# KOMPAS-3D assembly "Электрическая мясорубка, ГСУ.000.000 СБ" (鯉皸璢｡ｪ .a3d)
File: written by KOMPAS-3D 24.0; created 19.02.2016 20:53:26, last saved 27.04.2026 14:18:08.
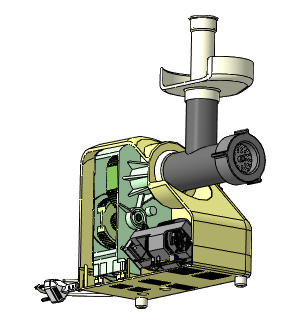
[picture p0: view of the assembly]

Document properties: Автор: Аня; Полное имя файла: C:\Users\USG_411.STUD\Desktop\ГМ2704_411-23\Мясорубка.a3d

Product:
- Component [detail]: Основание корпуса  | pos. 1  | Материал: Фторопласт-4  ГОСТ 10007-80 Е (density 2200 kg/m3); Масса: 0.272568; Автор: Аня; source file: Задание_ГМ-личная номинация\Задание_ВУЗ\Модели\Основание корпуса.m3d
- Component [detail]: Амортизатор  | pos. 10  | Масса: 0.016894; Автор: Аня; source file: Задание_ГМ-личная номинация\Задание_ВУЗ\Модели\Амортизатор (4 шт).m3d
- Component [detail]: Амортизатор  | pos. 11  | Масса: 0.016894; Автор: Аня; source file: Задание_ГМ-личная номинация\Задание_ВУЗ\Модели\Амортизатор (4 шт).m3d
- Component [detail]: Амортизатор  | pos. 12  | Масса: 0.016894; Автор: Аня; source file: Задание_ГМ-личная номинация\Задание_ВУЗ\Модели\Амортизатор (4 шт).m3d
- Component [detail]: Амортизатор  | pos. 13  | Масса: 0.016894; Автор: Аня; source file: Задание_ГМ-личная номинация\Задание_ВУЗ\Модели\Амортизатор (4 шт).m3d
- Component [detail]: Подушечка  | pos. 14  | Масса: 0.003215; Автор: Аня; source file: Задание_ГМ-личная номинация\Задание_ВУЗ\Модели\Подушечка .m3d
- Component [detail]: Подушечка  | pos. 15  | Масса: 0.003215; Автор: Аня; source file: Задание_ГМ-личная номинация\Задание_ВУЗ\Модели\Подушечка .m3d
- Component [detail]: Подушечка  | pos. 16  | Масса: 0.003215; Автор: Аня; source file: Задание_ГМ-личная номинация\Задание_ВУЗ\Модели\Подушечка .m3d
- Component [detail]: Подушечка  | pos. 17  | Масса: 0.003215; Автор: Аня; source file: Задание_ГМ-личная номинация\Задание_ВУЗ\Модели\Подушечка .m3d
- Component [detail]: Подушечка  | pos. 18  | Масса: 0.003215; Автор: Аня; source file: Задание_ГМ-личная номинация\Задание_ВУЗ\Модели\Подушечка .m3d
- Component [detail]: Подушечка  | pos. 19  | Масса: 0.003215; Автор: Аня; source file: Задание_ГМ-личная номинация\Задание_ВУЗ\Модели\Подушечка .m3d
- Component [detail]: Подушечка  | pos. 20  | Масса: 0.003215; Автор: Аня; source file: Задание_ГМ-личная номинация\Задание_ВУЗ\Модели\Подушечка .m3d
- Component [detail]: Подушечка  | pos. 21  | Масса: 0.003215; Автор: Аня; source file: Задание_ГМ-личная номинация\Задание_ВУЗ\Модели\Подушечка .m3d
- Component [assembly]: Редуктор  | pos. 2  | Масса: 2.986384; Автор: Аня; source file: Задание_ГМ-личная номинация\Задание_ВУЗ\Модели\Сборка редуктора.a3d
- Component [assembly]: Выключатель  | pos. 4  | Масса: 0.033755; Автор: Аня; source file: Задание_ГМ-личная номинация\Задание_ВУЗ\Модели\Выключатель.a3d
- Component [detail]: Плата  | pos. 5  | Масса: 0.019638; Автор: Аня; source file: Задание_ГМ-личная номинация\Задание_ВУЗ\Модели\Плата.m3d
- Component [assembly]: Сборка внешних деталей мясорубки  | pos. 6  | Масса: 5.888839; Автор: Аня; source file: Задание_ГМ-личная номинация\Задание_ВУЗ\Модели\Вторая сборка.a3d
- Component [detail]: Стопорный болт  | pos. 7  | Масса: 0.088582; Автор: Аня; source file: Задание_ГМ-личная номинация\Задание_ВУЗ\Модели\Стопорный болт.m3d
- Component [detail]: Вилка  | pos. 8  | Масса: 0.091381; Автор: Аня; source file: Задание_ГМ-личная номинация\Задание_ВУЗ\Модели\Вилка.m3d
- Component [detail]: Держатель провода  | pos. 9  | Масса: 0.003792; Автор: Аня; source file: Задание_ГМ-личная номинация\Задание_ВУЗ\Модели\Держатель провода.m3d
- Body: Тело 3  | qty 1
    Масса: 0.039235
- Component [standard]: Шайба A 4 ГОСТ 6958-78  | qty 4  | Масса: 0.000774; Раздел спецификации: Стандартные изделия; Рассекать на разрезах: no
- Component [standard]: Шуруп 1-4x20.019 ГОСТ 1144-80  | qty 4  | pos. 36  | Материал: Сталь 08кп ГОСТ 1050-2013 (density 7871 kg/m3); Масса: 0.00198; Раздел спецификации: Стандартные изделия; Рассекать на разрезах: no; additional columns: BOSimple***Material:aed9f2af-caf6-4059-826c-b94d4af93e47
- Component [assembly]: Двигатель  | designation ГСУ.001.000  | qty 1  | Масса: 0.738912; Автор: USG_411; source file: Двигатель мясорубки\ГСУ.001.000 ЭСБ - Двигатель.a3d
- Part/product: Электрическая мясорубка  | designation ГСУ.000.000 СБ
    Масса: 9.517468

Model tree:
1. Сечение поверхностью:1
2. Смещенная плоскость:1
     Расстояние = 15
3. Смещенная плоскость:2
     Расстояние = 63
4. Эскиз:1
5. Эскиз:3  (with: Грань.Операция выдавливания:2)
6. Эскиз:4  (with: Грань.Операция выдавливания:6, Ребро.Операция выдавливания:6)
7. Эскиз:6  (with: Грань.Операция выдавливания:2, Ребро.Вырезать элемент выдавливания:14)
8. Эскиз:7  (with: Грань.Вырезать элемент выдавливания:1, Ребро.Вырезать элемент выдавливания:2)
9. Смещенная плоскость:3  (with: Грань.Операция выдавливания:2)
     Расстояние = 12
10. Эскиз:8  (with: Ребро.Операция выдавливания:1)
11. Эскиз:9  (with: Грань.Операция выдавливания:6, Ребро.Вырезать элемент выдавливания:14)
12. Эскиз:10  (with: Грань.Операция выдавливания:2, Ребро.Вырезать элемент выдавливания:14)
13. Эскиз:11  (with: Грань.Операция выдавливания:2)
14. Эскиз:12  (with: Грань.Операция выдавливания:7)
15. Эскиз:13  (with: Грань.Операция выдавливания:1, Ребро.Вырезать элемент выдавливания:20)
16. Сплайн:4
     Координата X = 24.0569; Координата Y = 47.5876; Координата Z = 4.9171; Координата X = -2.76426; Координата Y = 55.0577; Координата Z = 3.36768; Координата X = -16.3145; Координата Y = 63.0116; Координата Z = 3; Координата X = -38.7823; Координата Y = 63; Координата Z = 2.99512; Координата X = -61.2823; Координата Y = 63; Координата Z = 2.99512; Координата X = -82; Координата Y = 30.4165; Координата Z = -3.17361; Координата X = -100; Координата Z = -10; Координата X = -102; Координата Z = -10; Координата X = -120.657; Координата Y = -31.7341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
17. Кинематическая операция:3
     Длина траектории = 519.475
18. Эскиз:14  (with: Грань.Кинематическая операция:3)
19. Эскиз:15  (with: Грань.Операция выдавливания:2)
20. Смещенная плоскость:5  (with: Грань.Вырезать элемент выдавливания:1)
     Расстояние = 3
21. Эскиз:16
22. Эскиз:17  (with: Грань.Кинематическая операция:3)
23. Смещенная плоскость:6  (with: Грань.Операция выдавливания:1)
     Расстояние = 2
24. Эскиз:20
25. Сплайн:7
     Координата X = 24.0569; Координата Y = 46.8619; Координата Z = 4.87679; Координата X = 24.0569; Координата Y = 38.923; Координата Z = -0.744157; Координата X = 9.1117; Координата Y = 32; Координата Z = -6.60744; Порядок = 4
26. Кинематическая операция:7
     Длина траектории = 28.248
27. Эскиз:21  (with: Грань.Операция выдавливания:1, Ребро.Операция выдавливания:1)
28. Эскиз:22  (with: Грань.Кинематическая операция:3)
29. Смещенная плоскость:7  (with: Грань.Операция выдавливания:2)
     Расстояние = 2
30. Смещенная плоскость:8  (with: Грань.Вырезать элемент выдавливания:1)
     Расстояние = 7
31. Эскиз:24
32. Эскиз:26
33. Сплайн:9
     Координата X = 24.0569; Координата Y = 48.3019; Координата Z = 4.84943; Координата X = 34.1389; Координата Y = 35.7895; Координата Z = 8; Координата X = 50.0249; Координата Y = 30.353; Координата Z = 8; Координата X = 53.724; Координата Y = 30.4898; Координата Z = 4; Координата X = 46.724; Координата Y = 30.4898; Координата Z = 4; Порядок = 4
34. Эскиз:27  (with: Грань.Кинематическая операция:3)
35. Кинематическая операция:9
     Длина траектории = 49.3177
36. Смещенная плоскость:9  (with: Грань.Операция выдавливания:1)
     Расстояние = 2
37. Эскиз:28  (with: Ребро.Вырезать элемент выдавливания:1)
38. Эскиз:30  (with: Грань.Операция выдавливания:1, Ребро.Операция выдавливания:1)
39. Эскиз:33  (with: Грань.Операция выдавливания:1, Ребро.Операция выдавливания:1)
40. Смещенная плоскость:10  (with: Грань.Вырезать элемент выдавливания:1)
     Расстояние = 5
41. Эскиз:34
42. Смещенная плоскость:11  (with: Грань.Вырезать элемент выдавливания:1)
     Расстояние = 6
43. Эскиз:35  (with: Грань.Вырезать элемент выдавливания:1)
44. Смещенная плоскость:12  (with: Грань.Операция выдавливания:2)
     Расстояние = 6
45. Эскиз:36  (with: Ребро.Скругление:1)
46. Смещенная плоскость:13  (with: Грань.Вырезать элемент выдавливания:1)
     Расстояние = 6
47. Эскиз:39  (with: Ребро.Вырезать элемент выдавливания:1, Ребро.Скругление:5)
48. Эскиз:40  (with: Грань.Операция выдавливания:1, Ребро.Операция выдавливания:1)
49. Смещенная плоскость:15  (with: Грань.Операция выдавливания:1)
     Расстояние = 32
50. Смещенная плоскость:16  (with: Грань.Вырезать элемент выдавливания:1)
     Расстояние = 41
51. Смещенная плоскость:24  (with: Грань.Операция выдавливания:1)
     Расстояние = 1.5
52. Эскиз:60
53. Эскиз:67
54. Смещенная плоскость:26  (with: Грань.Операция выдавливания:1)
     Расстояние = 2
55. Эскиз:68
56. Эскиз:69  (with: Ребро.Операция выдавливания:1)
57. Эскиз:72  (with: Ребро.Операция выдавливания:1, Вырезать элемент выдавливания:1, Операция выдавливания:1, Грань.Отверстие:1, Грань.Операция выдавливания:1, Грань.Элемент выдавливания:1)  (labels: Грань.Отверстие:1.Экземпляр ( 2, 1 ))
     Расстояние = 1.3; Ориентация = 2; Расстояние = 2

Referenced files in C:\Users\USG_411.STUD\Desktop\ГМ2704_411-23\Задание_ГМ-личная номинация\Задание_ВУЗ\Модели\: основание корпуса.m3d, Амортизатор (4 шт).m3d, Подушечка .m3d, Сборка редуктора.a3d, Выключатель.a3d, Плата.m3d, Вторая сборка.a3d, Стопорный болт.m3d, Вилка.m3d, Держатель провода.m3d
Referenced files in C:\Users\USG_411.STUD\DB\SI\Methods\Kompas\3D\: PLib_Washer_1_712.m3d, PLib_Screw_Shurup_900.m3d
Referenced files in C:\Users\USG_411.STUD\Desktop\ГМ2704_411-23\Двигатель мясорубки\: ГСУ.001.000 ЭСБ - Двигатель.a3d
Referenced files in T:\ОИТОД\Электрическая мясорубка\Электрическая мясорубка\: Амортизатор (4 шт).m3d, Подушечка .m3d
Referenced files in C:\DB\SI\Methods\Kompas\3D\: PLib_Washer_1_712.m3d, PLib_Screw_Shurup_900.m3d
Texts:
  Крепежное изделие ГОСТ
  BOSimple***PART:9cab8f69-1b85-68b4-05a8-15578942df64***SHORTLOC:Root±140±10±10±60±10±20[Нет;Без покрытия;Без указания материала;-;4]
  BOSimple***PART:990cabac-cbed-c4a6-76a4-a34520e752f7***SHORTLOC:A86A9_907A25C3CFA14727[9;Цинковое, хроматированное;4;20;Сталь 08кп ГОСТ 1050-2013]
  BOSimple***Material:aed9f2af-caf6-4059-826c-b94d4af93e47
  Программные изделия  и базы данных
  ГСУ.000.000 СБ
  Точка начала. Х
  Точка начала. Y
  Точка начала. Z
  Амортизатор (1)
  Амортизатор (2)
  Амортизатор (3)
  Амортизатор (4)
  Подушечка (1)
  Подушечка (2)
  Подушечка (3)
  Подушечка (4)
  Подушечка (5)
  Подушечка (6)
  Подушечка (7)
  Подушечка (8)
  Шайба A 4 ГОСТ 6958-78 (1)
  Шайба A 4 ГОСТ 6958-78 (2)
  Шайба A 4 ГОСТ 6958-78 (3)
  Шайба A 4 ГОСТ 6958-78 (4)
  Шуруп 1-4x20.019 ГОСТ 1144-80 (1)
  head2
  head4
  groove1
  fillet4
  head3
  groove4
  head5
  fillet1
  groove2
  groove3
  fillet2
  groove5
  head1
  Шуруп 1-4x20.019 ГОСТ 1144-80 (2)
  Шуруп 1-4x20.019 ГОСТ 1144-80 (3)
  Шуруп 1-4x20.019 ГОСТ 1144-80 (4)
  ГСУ.001.000 Двигатель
